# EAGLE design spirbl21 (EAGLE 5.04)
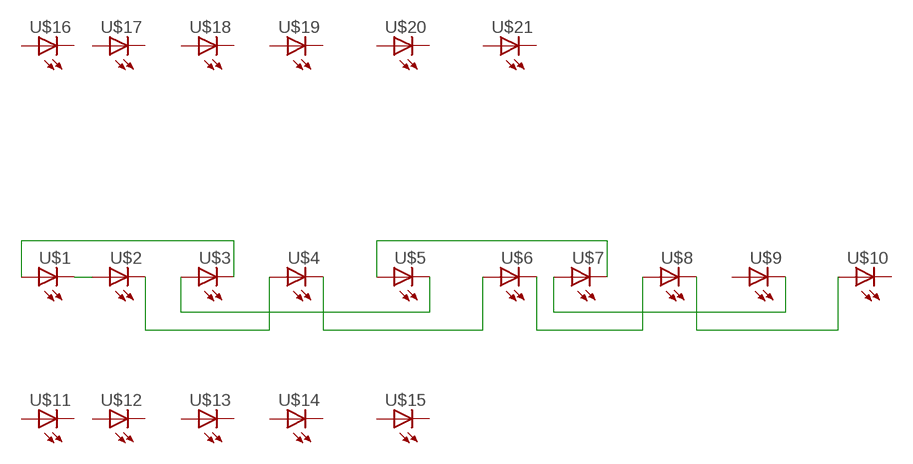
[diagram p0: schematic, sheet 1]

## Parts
U$1  LED5MM  [LED5MM]
U$2  LED5MM  [LED5MM]
U$3  LED5MM  [LED5MM]
U$4  LED5MM  [LED5MM]
U$5  LED5MM  [LED5MM]
U$6  LED5MM  [LED5MM]
U$7  LED5MM  [LED5MM]
U$8  LED5MM  [LED5MM]
U$9  LED5MM  [LED5MM]
U$10  LED5MM  [LED5MM]
U$11  LED5MM  [LED5MM]
U$12  LED5MM  [LED5MM]
U$13  LED5MM  [LED5MM]
U$14  LED5MM  [LED5MM]
U$15  LED5MM  [LED5MM]
U$16  LED5MM  [LED5MM]
U$17  LED5MM  [LED5MM]
U$18  LED5MM  [LED5MM]
U$19  LED5MM  [LED5MM]
U$20  LED5MM  [LED5MM]
U$21  LED5MM  [LED5MM]

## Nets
N$1: U$1.K(C) U$2.A
N$2: U$2.K(C) U$4.A
N$3: U$4.K(C) U$6.A
N$4: U$6.K(C) U$8.A
N$5: U$8.K(C) U$10.A
N$6: U$1.A U$3.K(C)
N$7: U$3.A U$5.K(C)
N$8: U$5.A U$7.K(C)
N$9: U$7.A U$9.K(C)
Unconnected: U$9.A U$10.K(C) U$11.A U$11.K(C) U$12.A U$12.K(C) U$13.A U$13.K(C) U$14.A U$14.K(C) U$15.A U$15.K(C) U$16.A U$16.K(C) U$17.A U$17.K(C) U$18.A U$18.K(C) U$19.A U$19.K(C) U$20.A U$20.K(C) U$21.A U$21.K(C)

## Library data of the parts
U$1-U$21 = led(2):LED: LED

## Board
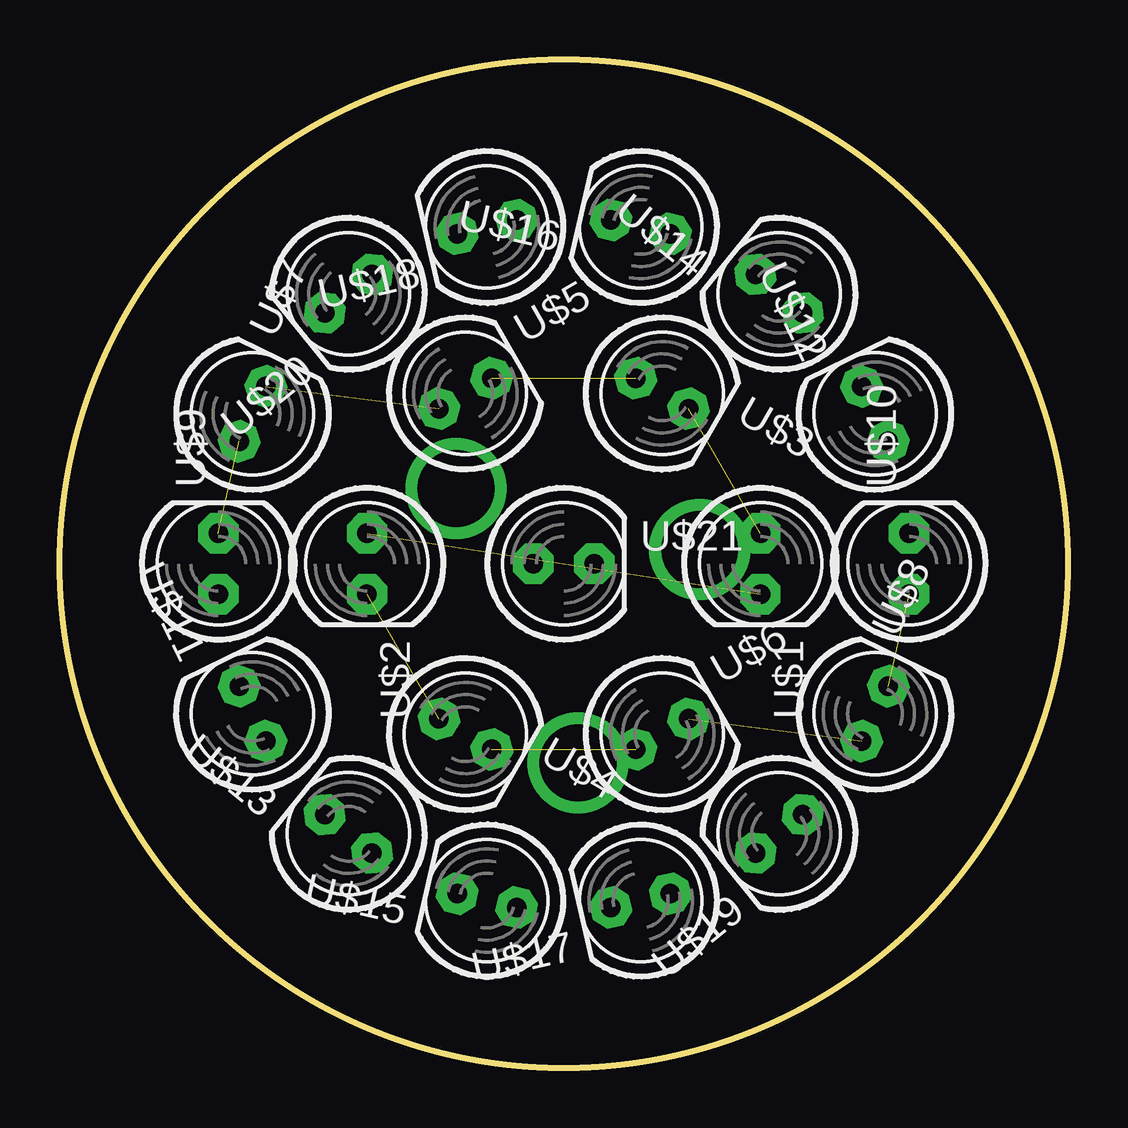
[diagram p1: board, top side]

Size 42 x 42 mm. Coordinates in mm from the lower left corner, seen from the top.
Outline: circle at 21,21 radius 21
Copper layers (1*16): Top 0.035mm / dielectric 1.5mm / Bottom 0.035mm
Design rules "default": minimum track width 10mil, minimum drill 24mil, track to track 8mil, track to pad 8mil, pad to pad 8mil, via to via 8mil, smd to smd 8mil, copper to edge 40mil, drill to drill 8mil, minimum pad ring 10mil, minimum via ring 8mil, stop-mask expansion 4mil, vias tented up to drill 0mil, thermal gap 10mil

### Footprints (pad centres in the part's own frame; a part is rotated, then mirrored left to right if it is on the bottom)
LED5MM = drill 0.813 pad 1.676 octagon: A -1.27,0; K 1.27,0

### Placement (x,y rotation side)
U$1  29.2,21 270 top
U$2  12.8,21 270 top
U$3  25.1,28.1 330 top
U$4  16.9,13.9 330 top
U$5  16.9,28.1 30 top
U$6  25.1,13.9 30 top
U$7  8.03,27.25 64 top
U$8  33.97,14.75 64 top
U$9  6.6,21 90 top
U$10  35.4,21 90 top
U$11  8.03,14.75 116 top
U$12  33.97,27.25 116 top
U$13  12.02,9.74 141 top
U$14  29.98,32.26 141 top
U$15  17.8,6.96 167 top
U$16  24.2,35.04 167 top
U$17  24.2,6.96 193 top
U$18  17.8,35.04 193 top
U$19  29.98,9.74 219 top
U$20  12.02,32.26 219 top
U$21  21,21 0 top

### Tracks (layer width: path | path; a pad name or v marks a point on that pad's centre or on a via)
HOL1  (via drill 3.2)
  other vias: 21.59,12.7
HOL2  (via drill 3.2)
  other vias: 16.51,24.13
HOL3  (via drill 3.2)
  other vias: 26.67,21.59
N$1  (1 unrouted)
N$2  (1 unrouted)
N$3  (1 unrouted)
N$4  (1 unrouted)
N$5  (1 unrouted)
N$6  (1 unrouted)
N$7  (1 unrouted)
N$8  (1 unrouted)
N$9  (1 unrouted)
